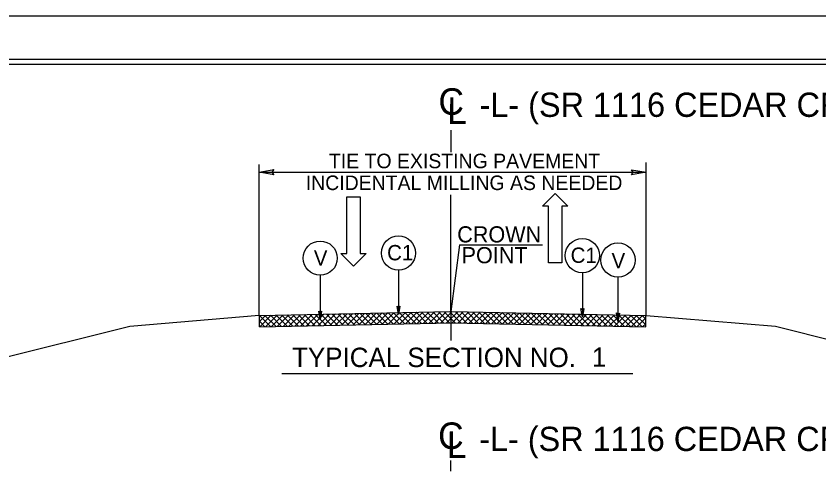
# Model space of a CAD drawing. Extents: x 573732 to 574187, y -53389 to -53257.
# Drawn here: x 573830.28 to 573879.96, y -53285.14 to -53256.95 of the extents above; entities that cross this region are included whole.
import ezdxf

# ---------------------------------------------------------------- set-up
doc = ezdxf.new("R2010")
doc.units = 0
for name, color, linetype in [('Old_Level_1', 7, 'Continuous'), ('Old_Level_11', 7, 'Continuous'), ('Old_Level_3', 7, 'Continuous'), ('Old_Level_4', 7, 'Continuous'), ('Sheet Cutting Line CELL', 7, 'Continuous'), ('Sheet Plot Border Inside CELL', 7, 'Continuous'), ('Sheet Plot Border Outside CELL', 7, 'Continuous'), ('Sheet Typical CELL', 7, 'Continuous'), ('Typical ID Circle CELL', 7, 'Continuous'), ('Typical Terminator CELL', 7, 'Continuous'), ('Typical Text Centerline CELL', 7, 'Continuous'), ('Typical Text ID Circle CELL', 7, 'Continuous')]:
    doc.layers.add(name, color=color, linetype=linetype)

# ---------------------------------------------------------------- blocks, each defined once
blk = doc.blocks.new('TERMINATOR')
at = {"layer": 'Typical Terminator CELL'}
blk.add_lwpolyline([(-0.469, 0.081), (0, 0), (-0.471, -0.083), (-0.411, 0)], close=True, dxfattribs=at)

msp = doc.modelspace()

# ---------------------------------------------------------------- linework, layer by layer
at = {"layer": 'Old_Level_1'}
for p, q in [((573857.204, -53265.357), (573857.204, -53264)), ((573857.171, -53275.224), (573857.171, -53268.009)), ((573845.319, -53275.471), (573857.171, -53275.224)), ((573852.936, -53276.012), (573853.651, -53275.297)), ((573853.297, -53276.005), (573854.012, -53275.29)), ((573854.328, -53275.983), (573853.642, -53275.298)), ((573853.658, -53275.997), (573854.373, -53275.282)), ((573854.674, -53275.976), (573853.988, -53275.29)), ((573854.019, -53275.99), (573854.734, -53275.275)), ((573855.021, -53275.969), (573854.335, -53275.283)), ((573854.38, -53275.982), (573855.095, -53275.267)), ((573855.367, -53275.962), (573854.681, -53275.276)), ((573854.741, -53275.975), (573855.456, -53275.26)), ((573855.713, -53275.954), (573855.027, -53275.269)), ((573855.102, -53275.967), (573855.817, -53275.252)), ((573856.06, -53275.947), (573855.374, -53275.262)), ((573855.463, -53275.96), (573856.178, -53275.245)), ((573856.406, -53275.94), (573855.72, -53275.254)), ((573855.824, -53275.952), (573856.539, -53275.237)), ((573856.752, -53275.933), (573856.067, -53275.247)), ((573856.186, -53275.945), (573856.9, -53275.23)), ((573857.099, -53275.926), (573856.413, -53275.24)), ((573856.547, -53275.937), (573857.258, -53275.226)), ((573857.457, -53275.93), (573856.759, -53275.233)), ((573856.908, -53275.93), (573857.604, -53275.233)), ((573857.818, -53275.938), (573857.106, -53275.225)), ((573857.171, -53275.224), (573869.255, -53275.476)), ((573857.171, -53275.224), (573857.171, -53277.003)), ((573857.265, -53275.926), (573857.95, -53275.24)), ((573858.179, -53275.945), (573857.464, -53275.23)), ((573857.611, -53275.933), (573858.297, -53275.248)), ((573858.54, -53275.953), (573857.825, -53275.238)), ((573857.957, -53275.94), (573858.643, -53275.255)), ((573858.901, -53275.96), (573858.186, -53275.245)), ((573858.304, -53275.948), (573858.989, -53275.262)), ((573859.262, -53275.968), (573858.547, -53275.253)), ((573858.65, -53275.955), (573859.336, -53275.269)), ((573859.623, -53275.975), (573858.908, -53275.26)), ((573858.996, -53275.962), (573859.682, -53275.276)), ((573859.984, -53275.983), (573859.269, -53275.268)), ((573859.343, -53275.969), (573860.029, -53275.284)), ((573860.345, -53275.99), (573859.63, -53275.275)), ((573859.689, -53275.977), (573860.375, -53275.291)), ((573860.706, -53275.998), (573859.991, -53275.283)), ((573860.035, -53275.984), (573860.721, -53275.298)), ((573861.067, -53276.005), (573860.352, -53275.29)), ((573861.428, -53276.013), (573860.714, -53275.298)), ((573845.319, -53275.471), (573837.319, -53276.137)), ((573845.333, -53275.837), (573845.707, -53275.463)), ((573845.333, -53275.483), (573845.346, -53275.47)), ((573845.333, -53276.171), (573845.333, -53275.471)), ((573846.016, -53276.156), (573845.333, -53275.474)), ((573845.353, -53276.17), (573846.068, -53275.455)), ((573846.362, -53276.149), (573845.676, -53275.463)), ((573845.714, -53276.163), (573846.429, -53275.448)), ((573846.708, -53276.142), (573846.023, -53275.456)), ((573846.076, -53276.155), (573846.79, -53275.44)), ((573847.055, -53276.135), (573846.369, -53275.449)), ((573846.437, -53276.148), (573847.151, -53275.433)), ((573847.401, -53276.128), (573846.715, -53275.442)), ((573846.798, -53276.14), (573847.513, -53275.425)), ((573847.747, -53276.12), (573847.062, -53275.435)), ((573847.159, -53276.133), (573847.874, -53275.418)), ((573848.094, -53276.113), (573847.408, -53275.427)), ((573847.52, -53276.125), (573848.235, -53275.41)), ((573848.44, -53276.106), (573847.754, -53275.42)), ((573847.881, -53276.118), (573848.596, -53275.403)), ((573848.786, -53276.099), (573848.101, -53275.413)), ((573848.242, -53276.11), (573848.957, -53275.395)), ((573849.133, -53276.092), (573848.447, -53275.406)), ((573848.603, -53276.103), (573849.318, -53275.388)), ((573849.479, -53276.084), (573848.793, -53275.399)), ((573848.964, -53276.095), (573849.679, -53275.38)), ((573849.825, -53276.077), (573849.14, -53275.391)), ((573849.325, -53276.088), (573850.04, -53275.373)), ((573850.172, -53276.07), (573849.486, -53275.384)), ((573849.686, -53276.08), (573850.401, -53275.365)), ((573850.518, -53276.063), (573849.832, -53275.377)), ((573850.047, -53276.072), (573850.762, -53275.358)), ((573850.864, -53276.055), (573850.179, -53275.37)), ((573850.408, -53276.065), (573851.123, -53275.35)), ((573851.211, -53276.048), (573850.525, -53275.363)), ((573850.769, -53276.057), (573851.484, -53275.343)), ((573851.557, -53276.041), (573850.871, -53275.355)), ((573851.131, -53276.05), (573851.845, -53275.335)), ((573851.903, -53276.034), (573851.218, -53275.348)), ((573851.492, -53276.042), (573852.207, -53275.327)), ((573852.25, -53276.027), (573851.564, -53275.341)), ((573851.853, -53276.035), (573852.568, -53275.32)), ((573852.596, -53276.019), (573851.91, -53275.334)), ((573852.214, -53276.027), (573852.929, -53275.312)), ((573852.942, -53276.012), (573852.257, -53275.326)), ((573852.575, -53276.02), (573853.29, -53275.305)), ((573853.289, -53276.005), (573852.603, -53275.319)), ((573853.635, -53275.998), (573852.949, -53275.312)), ((573853.982, -53275.991), (573853.296, -53275.305)), ((573860.382, -53275.991), (573861.068, -53275.305)), ((573860.728, -53275.998), (573861.414, -53275.313)), ((573861.074, -53276.005), (573861.76, -53275.32)), ((573861.789, -53276.02), (573861.075, -53275.305)), ((573861.421, -53276.013), (573862.107, -53275.327)), ((573862.151, -53276.028), (573861.436, -53275.313)), ((573861.767, -53276.02), (573862.453, -53275.334)), ((573862.512, -53276.035), (573861.797, -53275.321)), ((573862.113, -53276.027), (573862.799, -53275.341)), ((573862.873, -53276.043), (573862.158, -53275.328)), ((573862.46, -53276.034), (573863.146, -53275.349)), ((573863.234, -53276.05), (573862.519, -53275.336)), ((573862.806, -53276.042), (573863.492, -53275.356)), ((573863.595, -53276.058), (573862.88, -53275.343)), ((573863.153, -53276.049), (573863.838, -53275.363)), ((573863.956, -53276.066), (573863.241, -53275.351)), ((573863.499, -53276.056), (573864.185, -53275.37)), ((573864.317, -53276.073), (573863.602, -53275.358)), ((573863.845, -53276.063), (573864.531, -53275.377)), ((573864.678, -53276.081), (573863.963, -53275.366)), ((573864.192, -53276.07), (573864.877, -53275.385)), ((573865.039, -53276.088), (573864.324, -53275.373)), ((573864.538, -53276.078), (573865.224, -53275.392)), ((573865.4, -53276.096), (573864.685, -53275.381)), ((573864.884, -53276.085), (573865.57, -53275.399)), ((573865.761, -53276.103), (573865.046, -53275.388)), ((573865.231, -53276.092), (573865.916, -53275.406)), ((573866.122, -53276.111), (573865.408, -53275.396)), ((573865.577, -53276.099), (573866.263, -53275.414)), ((573866.484, -53276.118), (573865.769, -53275.403)), ((573865.923, -53276.107), (573866.609, -53275.421)), ((573866.845, -53276.126), (573866.13, -53275.411)), ((573866.27, -53276.114), (573866.955, -53275.428)), ((573867.206, -53276.133), (573866.491, -53275.418)), ((573866.616, -53276.121), (573867.302, -53275.435)), ((573867.567, -53276.141), (573866.852, -53275.426)), ((573866.962, -53276.128), (573867.648, -53275.442)), ((573867.928, -53276.148), (573867.213, -53275.433)), ((573867.309, -53276.135), (573867.994, -53275.45)), ((573868.289, -53276.156), (573867.574, -53275.441)), ((573867.655, -53276.143), (573868.341, -53275.457)), ((573868.65, -53276.163), (573867.935, -53275.448)), ((573868.001, -53276.15), (573868.687, -53275.464)), ((573869.011, -53276.171), (573868.296, -53275.456)), ((573868.348, -53276.157), (573869.033, -53275.471)), ((573869.24, -53276.046), (573868.657, -53275.463)), ((573868.694, -53276.164), (573869.24, -53275.618)), ((573869.24, -53275.693), (573869.018, -53275.471)), ((573869.24, -53276.176), (573869.24, -53275.476)), ((573869.261, -53275.463), (573877.261, -53276.129)), ((573837.319, -53276.137), (573826.579, -53278.822)), ((573845.669, -53276.164), (573845.333, -53275.827)), ((573845.333, -53276.171), (573857.269, -53275.922)), ((573857.171, -53275.924), (573869.24, -53276.176)), ((573869.04, -53276.171), (573869.24, -53275.972)), ((573877.261, -53276.129), (573889.395, -53279.163)), ((573846.713, -53279.06), (573868.434, -53279.06))]:
    msp.add_line(p, q, dxfattribs=at)
at = {"layer": 'Old_Level_11'}
for points in [[(573846.219, -53266.758), (573845.319, -53266.603), (573846.224, -53266.443), (573846.109, -53266.603)], [(573868.361, -53266.448), (573869.261, -53266.603), (573868.356, -53266.763), (573868.471, -53266.603)]]:
    msp.add_lwpolyline(points, close=True, dxfattribs=at)
at = {"layer": 'Old_Level_3'}
for p, q in [((573845.319, -53275.471), (573845.319, -53266.125)), ((573869.261, -53275.463), (573869.261, -53266.005)), ((573845.319, -53266.603), (573869.261, -53266.603)), ((573857.71, -53271.094), (573857.171, -53275.224)), ((573857.71, -53271.094), (573862.851, -53271.094))]:
    msp.add_line(p, q, dxfattribs=at)
at = {"layer": 'Old_Level_4'}
for p, q in [((573850.739, -53271.625), (573850.739, -53268.125)), ((573850.739, -53268.125), (573851.564, -53268.125)), ((573851.564, -53268.125), (573851.564, -53271.625)), ((573862.852, -53268.714), (573863.627, -53267.926)), ((573863.627, -53267.926), (573864.427, -53268.714)), ((573863.227, -53268.714), (573862.852, -53268.714)), ((573863.227, -53272.214), (573863.227, -53268.714)), ((573864.427, -53268.714), (573864.052, -53268.714)), ((573864.052, -53268.714), (573864.052, -53272.214)), ((573851.164, -53272.412), (573850.364, -53271.625)), ((573850.364, -53271.625), (573850.739, -53271.625)), ((573851.939, -53271.625), (573851.164, -53272.412)), ((573851.564, -53271.625), (573851.939, -53271.625)), ((573864.052, -53272.214), (573863.227, -53272.214))]:
    msp.add_line(p, q, dxfattribs=at)
at = {"layer": 'Sheet Cutting Line CELL'}
msp.add_line((573984.302, -53256.948), (573782.222, -53256.948), dxfattribs=at)
at = {"layer": 'Sheet Plot Border Inside CELL'}
msp.add_lwpolyline([(573983.762, -53259.642), (573783.782, -53259.642), (573783.782, -53386.254), (573983.762, -53386.254)], close=True, dxfattribs=at)
at = {"layer": 'Sheet Plot Border Outside CELL'}
msp.add_lwpolyline([(573984.302, -53256.948), (573782.222, -53256.948), (573782.222, -53388.948), (573984.302, -53388.948)], close=True, dxfattribs=at)
at = {"layer": 'Sheet Typical CELL'}
msp.add_lwpolyline([(573982.262, -53259.948), (573802.262, -53259.948), (573802.262, -53385.948), (573982.262, -53385.948)], close=True, dxfattribs=at)
at = {"layer": 'Typical ID Circle CELL'}
for p, q in [((573853.94, -53272.665), (573853.94, -53275.399)), ((573849.096, -53272.975), (573849.096, -53275.709)), ((573865.321, -53272.822), (573865.321, -53275.556)), ((573867.518, -53273.096), (573867.518, -53275.83))]:
    msp.add_line(p, q, dxfattribs=at)
for centre in [(573853.94, -53271.607), (573865.321, -53271.765), (573849.096, -53271.918), (573867.518, -53272.038)]:
    msp.add_circle(centre, 1.058, dxfattribs=at)
at = {"layer": 'Typical Text Centerline CELL'}
msp.add_line((573857.171, -53285.095), (573857.171, -53284.438), dxfattribs=at)

# ---------------------------------------------------------------- block references
at = {"layer": 'Typical Terminator CELL', "xscale": 1.1, "yscale": 1.1, "rotation": -90}
for p in [(573849.096, -53275.709), (573853.94, -53275.399), (573865.321, -53275.556), (573867.518, -53275.83)]:
    msp.add_blockref('TERMINATOR', p, dxfattribs=at)

# ---------------------------------------------------------------- texts
at = {"layer": 'Old_Level_11'}
for s, p in [('CROWN', (573857.573, -53270.949)), ('POINT', (573857.845, -53272.235))]:
    msp.add_text(s, height=1, dxfattribs=at).set_placement(p)
at = {"layer": 'Old_Level_3'}
for s, height, p in [('TIE TO EXISTING PAVEMENT', 0.9, (573849.635, -53266.359)), ('INCIDENTAL MILLING AS NEEDED', 0.9, (573848.201, -53267.709)), ('TYPICAL SECTION NO.  ', 1.2, (573847.358, -53278.657)), ('1 ', 1.2, (573865.91, -53278.641))]:
    msp.add_text(s, height=height, dxfattribs=at).set_placement(p)
at = {"layer": 'Typical Text Centerline CELL'}
for p in [(573856.411, -53263.054), (573856.39, -53283.72)]:
    msp.add_text('C', height=1.64, dxfattribs=at).set_placement(p)
for s, height, rotation, p in [('-L- (SR 1116 CEDAR CREEK RD)', 1.5, 360, (573858.954, -53263.183)), ('L', 1.641, 359.9469, (573856.957, -53263.614)), ('L', 1.641, 359.9469, (573856.936, -53284.28)), ('-L- (SR 1116 CEDAR CREEK RD)', 1.5, 360, (573858.933, -53283.849))]:
    msp.add_text(s, height=height, rotation=rotation, dxfattribs=at).set_placement(p)
at = {"layer": 'Typical Text ID Circle CELL'}
for s, height, p in [('C1', 0.9469, (573853.236, -53272.054)), ('C1', 0.9469, (573864.592, -53272.212)), ('V', 0.947, (573848.701, -53272.376)), ('V', 0.947, (573867.123, -53272.55))]:
    msp.add_text(s, height=height, dxfattribs=at).set_placement(p)

doc.saveas('drawing.dxf')
